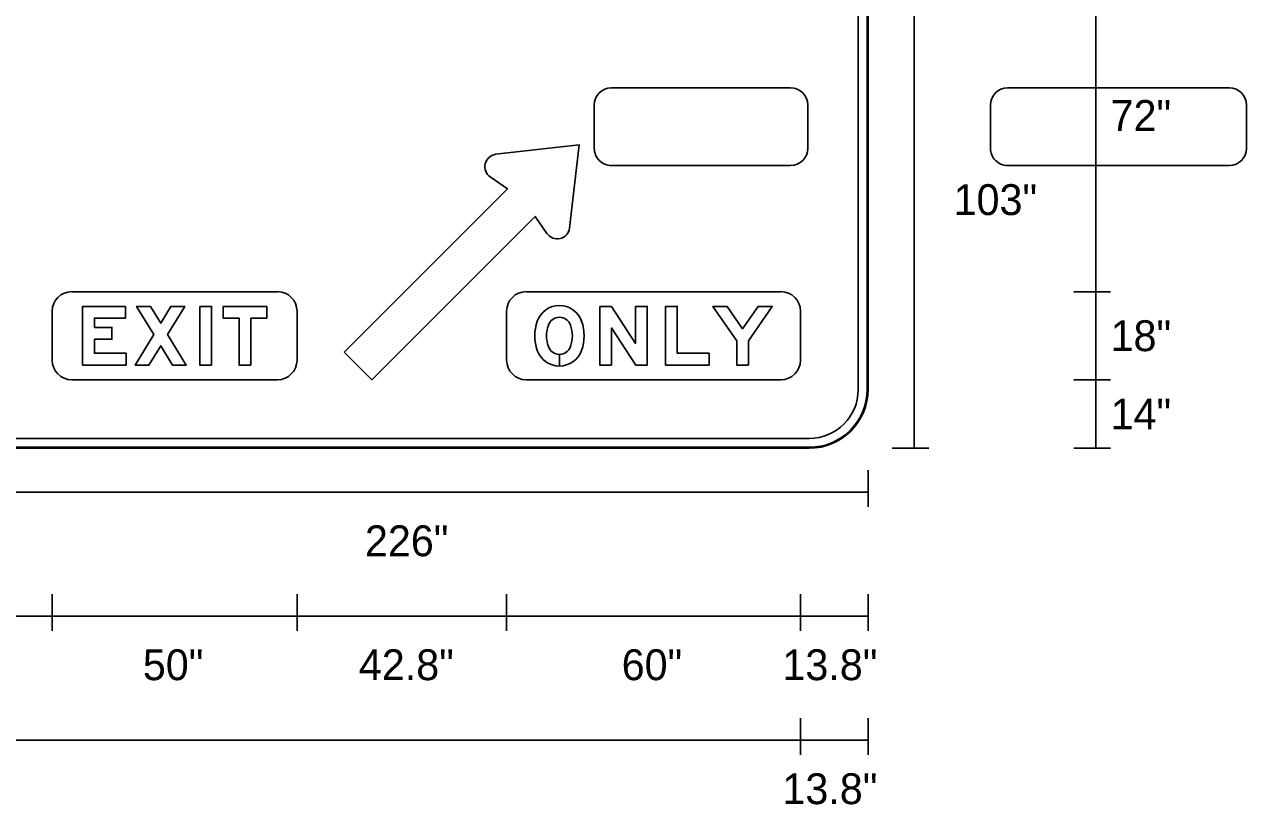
# Model space of a CAD drawing. Extents: x 531799 to 532094, y 1531149 to 1533620.
# Drawn here: x 531850.85 to 531874.42, y 1531200.2 to 1531215.25 of the extents above; entities that cross this region are included whole.
import ezdxf

# ---------------------------------------------------------------- set-up
doc = ezdxf.new("R2010")
doc.units = 0
for name, color, linetype in [('GSDims', 7, 'Continuous'), ('GSOutline', 7, 'Continuous'), ('SignPanel', 7, 'Continuous')]:
    doc.layers.add(name, color=color, linetype=linetype)

msp = doc.modelspace()

# ---------------------------------------------------------------- linework, layer by layer
at = {"layer": 'GSDims'}
for p, q in [((531868.008, 1531207.076), (531868.008, 1531229.171)), ((531871.513, 1531210.097), (531871.513, 1531216.896)), ((531871.088, 1531210.097), (531871.796, 1531210.097)), ((531871.088, 1531210.097), (531871.796, 1531210.097)), ((531871.513, 1531210.097), (531871.513, 1531208.398)), ((531871.088, 1531208.398), (531871.796, 1531208.398)), ((531871.088, 1531208.398), (531871.796, 1531208.398)), ((531871.513, 1531207.076), (531871.513, 1531208.398)), ((531867.583, 1531207.076), (531868.291, 1531207.076)), ((531871.088, 1531207.076), (531871.796, 1531207.076)), ((531867.118, 1531206.651), (531867.118, 1531205.943)), ((531821.609, 1531206.226), (531865.814, 1531206.226)), ((531865.814, 1531206.226), (531867.118, 1531206.226)), ((531851.387, 1531204.259), (531851.387, 1531203.551)), ((531856.108, 1531204.259), (531856.108, 1531203.551)), ((531860.149, 1531204.259), (531860.149, 1531203.551)), ((531865.814, 1531204.259), (531865.814, 1531203.551)), ((531865.814, 1531204.259), (531865.814, 1531203.551)), ((531867.118, 1531204.259), (531867.118, 1531203.551)), ((531821.609, 1531203.835), (531865.814, 1531203.835)), ((531865.814, 1531203.835), (531867.118, 1531203.835)), ((531865.814, 1531201.868), (531865.814, 1531201.16)), ((531865.814, 1531201.868), (531865.814, 1531201.16)), ((531867.118, 1531201.868), (531867.118, 1531201.16)), ((531821.609, 1531201.443), (531865.814, 1531201.443)), ((531865.814, 1531201.443), (531867.118, 1531201.443))]:
    msp.add_line(p, q, dxfattribs=at)
at = {"layer": 'GSOutline'}
for p, q in [((531866.929, 1531208.209), (531866.929, 1531228.038)), ((531867.118, 1531208.209), (531867.118, 1531228.038)), ((531865.626, 1531214.03), (531862.169, 1531214.03)), ((531874.088, 1531214.03), (531869.808, 1531214.03)), ((531861.839, 1531213.696), (531861.839, 1531212.863)), ((531865.955, 1531212.863), (531865.955, 1531213.696)), ((531869.479, 1531213.696), (531869.479, 1531212.863)), ((531874.418, 1531212.863), (531874.418, 1531213.696)), ((531862.169, 1531212.53), (531865.626, 1531212.53)), ((531869.808, 1531212.53), (531874.088, 1531212.53)), ((531817.263, 1531207.265), (531865.985, 1531207.265)), ((531817.263, 1531207.076), (531865.985, 1531207.076))]:
    msp.add_line(p, q, dxfattribs=at)
for radius in [1.133, 0.944]:
    msp.add_arc((531865.985, 1531208.209), radius, 270, 0, dxfattribs=at)
for centre, start_param, end_param in [((531862.169, 1531213.696), 0, 1.570796), ((531865.626, 1531213.696), 4.712389, 6.283185), ((531869.808, 1531213.696), 0, 1.570796), ((531874.088, 1531213.696), 4.712389, 6.283185), ((531862.169, 1531212.863), 1.570796, 3.141593), ((531865.626, 1531212.863), 3.141593, 4.712389), ((531869.808, 1531212.863), 1.570796, 3.141593), ((531874.088, 1531212.863), 3.141593, 4.712389)]:
    msp.add_ellipse(centre, major_axis=(0, 0.333), ratio=0.987826, start_param=start_param, end_param=end_param, dxfattribs=at)
at = {"layer": 'SignPanel'}
for p, q in [((531866.929, 1531228.038), (531866.929, 1531208.209)), ((531866.929, 1531228.038), (531866.929, 1531208.209)), ((531867.099, 1531228.038), (531867.099, 1531208.209)), ((531867.118, 1531208.209), (531867.118, 1531228.038)), ((531867.118, 1531208.209), (531867.118, 1531228.038)), ((531867.118, 1531208.209), (531867.118, 1531228.038)), ((531867.118, 1531208.209), (531867.118, 1531228.038)), ((531851.764, 1531210.097), (531855.73, 1531210.097)), ((531865.437, 1531210.097), (531860.527, 1531210.097)), ((531851.387, 1531208.776), (531851.387, 1531209.72)), ((531856.108, 1531209.72), (531856.108, 1531208.776)), ((531860.149, 1531209.72), (531860.149, 1531208.776)), ((531865.814, 1531208.776), (531865.814, 1531209.72)), ((531861.168, 1531208.661), (531861.168, 1531208.888)), ((531861.168, 1531208.888), (531861.168, 1531208.661)), ((531861.168, 1531208.661), (531861.168, 1531208.888)), ((531861.168, 1531208.888), (531861.168, 1531208.661)), ((531855.73, 1531208.398), (531851.764, 1531208.398)), ((531860.527, 1531208.398), (531865.437, 1531208.398)), ((531865.985, 1531207.095), (531817.263, 1531207.095)), ((531817.263, 1531207.076), (531865.985, 1531207.076)), ((531817.263, 1531207.076), (531865.985, 1531207.076)), ((531865.985, 1531207.265), (531817.265, 1531207.265)), ((531865.985, 1531207.265), (531817.265, 1531207.265)), ((531817.265, 1531207.076), (531865.985, 1531207.076)), ((531817.265, 1531207.076), (531865.985, 1531207.076))]:
    msp.add_line(p, q, dxfattribs=at)
for points in [[(531859.936, 1531212.747), (531861.547, 1531212.931), (531861.364, 1531211.32)], [(531857.014, 1531208.932), (531860.165, 1531212.083), (531859.835, 1531212.311)], [(531860.927, 1531211.219), (531860.699, 1531211.549), (531857.548, 1531208.398), (531857.014, 1531208.932)]]:
    msp.add_lwpolyline(points, dxfattribs=at)
for points in [[(531852.799, 1531209.814), (531852.799, 1531209.588), (531852.199, 1531209.588), (531852.199, 1531209.406), (531852.539, 1531209.406), (531852.539, 1531209.18), (531852.199, 1531209.18), (531852.199, 1531208.908), (531852.811, 1531208.908), (531852.811, 1531208.681), (531851.972, 1531208.681), (531851.972, 1531209.814)], [(531852.799, 1531209.814), (531852.799, 1531209.588), (531852.199, 1531209.588), (531852.199, 1531209.406), (531852.539, 1531209.406), (531852.539, 1531209.18), (531852.199, 1531209.18), (531852.199, 1531208.908), (531852.811, 1531208.908), (531852.811, 1531208.681), (531851.972, 1531208.681), (531851.972, 1531209.814)], [(531852.799, 1531209.814), (531852.799, 1531209.588), (531852.199, 1531209.588), (531852.199, 1531209.406), (531852.539, 1531209.406), (531852.539, 1531209.18), (531852.199, 1531209.18), (531852.199, 1531208.908), (531852.811, 1531208.908), (531852.811, 1531208.681), (531851.972, 1531208.681), (531851.972, 1531209.814)], [(531853.705, 1531208.681), (531853.478, 1531209.053), (531853.251, 1531208.681), (531852.985, 1531208.681), (531853.345, 1531209.271), (531853.014, 1531209.814), (531853.279, 1531209.814), (531853.478, 1531209.488), (531853.677, 1531209.814), (531853.943, 1531209.814), (531853.611, 1531209.271), (531853.971, 1531208.681)], [(531853.705, 1531208.681), (531853.478, 1531209.053), (531853.251, 1531208.681), (531852.985, 1531208.681), (531853.345, 1531209.271), (531853.014, 1531209.814), (531853.279, 1531209.814), (531853.478, 1531209.488), (531853.677, 1531209.814), (531853.943, 1531209.814), (531853.611, 1531209.271), (531853.971, 1531208.681)], [(531853.705, 1531208.681), (531853.478, 1531209.053), (531853.251, 1531208.681), (531852.985, 1531208.681), (531853.345, 1531209.271), (531853.014, 1531209.814), (531853.279, 1531209.814), (531853.478, 1531209.488), (531853.677, 1531209.814), (531853.943, 1531209.814), (531853.611, 1531209.271), (531853.971, 1531208.681)], [(531854.233, 1531209.814), (531854.459, 1531209.814), (531854.459, 1531208.681), (531854.233, 1531208.681)], [(531854.233, 1531209.814), (531854.459, 1531209.814), (531854.459, 1531208.681), (531854.233, 1531208.681)], [(531854.233, 1531209.814), (531854.459, 1531209.814), (531854.459, 1531208.681), (531854.233, 1531208.681)], [(531855.217, 1531208.681), (531854.99, 1531208.681), (531854.99, 1531209.588), (531854.684, 1531209.588), (531854.684, 1531209.814), (531855.522, 1531209.814), (531855.522, 1531209.588), (531855.217, 1531209.588)], [(531855.217, 1531208.681), (531854.99, 1531208.681), (531854.99, 1531209.588), (531854.684, 1531209.588), (531854.684, 1531209.814), (531855.522, 1531209.814), (531855.522, 1531209.588), (531855.217, 1531209.588)], [(531855.217, 1531208.681), (531854.99, 1531208.681), (531854.99, 1531209.588), (531854.684, 1531209.588), (531854.684, 1531209.814), (531855.522, 1531209.814), (531855.522, 1531209.588), (531855.217, 1531209.588)], [(531861.945, 1531209.814), (531862.171, 1531209.814), (531862.636, 1531209.1), (531862.636, 1531209.814), (531862.862, 1531209.814), (531862.862, 1531208.681), (531862.638, 1531208.681), (531862.171, 1531209.399), (531862.171, 1531208.681), (531861.945, 1531208.681)], [(531861.945, 1531209.814), (531862.171, 1531209.814), (531862.636, 1531209.1), (531862.636, 1531209.814), (531862.862, 1531209.814), (531862.862, 1531208.681), (531862.638, 1531208.681), (531862.171, 1531209.399), (531862.171, 1531208.681), (531861.945, 1531208.681)], [(531861.945, 1531209.814), (531862.171, 1531209.814), (531862.636, 1531209.1), (531862.636, 1531209.814), (531862.862, 1531209.814), (531862.862, 1531208.681), (531862.638, 1531208.681), (531862.171, 1531209.399), (531862.171, 1531208.681), (531861.945, 1531208.681)], [(531863.44, 1531208.908), (531864.052, 1531208.908), (531864.052, 1531208.681), (531863.213, 1531208.681), (531863.213, 1531209.814), (531863.44, 1531209.814)], [(531863.44, 1531208.908), (531864.052, 1531208.908), (531864.052, 1531208.681), (531863.213, 1531208.681), (531863.213, 1531209.814), (531863.44, 1531209.814)], [(531863.44, 1531208.908), (531864.052, 1531208.908), (531864.052, 1531208.681), (531863.213, 1531208.681), (531863.213, 1531209.814), (531863.44, 1531209.814)], [(531864.813, 1531208.681), (531864.586, 1531208.681), (531864.586, 1531209.146), (531864.127, 1531209.814), (531864.402, 1531209.814), (531864.699, 1531209.381), (531864.997, 1531209.814), (531865.272, 1531209.814), (531864.813, 1531209.146)], [(531864.813, 1531208.681), (531864.586, 1531208.681), (531864.586, 1531209.146), (531864.127, 1531209.814), (531864.402, 1531209.814), (531864.699, 1531209.381), (531864.997, 1531209.814), (531865.272, 1531209.814), (531864.813, 1531209.146)], [(531864.813, 1531208.681), (531864.586, 1531208.681), (531864.586, 1531209.146), (531864.127, 1531209.814), (531864.402, 1531209.814), (531864.699, 1531209.381), (531864.997, 1531209.814), (531865.272, 1531209.814), (531864.813, 1531209.146)]]:
    msp.add_lwpolyline(points, close=True, dxfattribs=at)
for centre, radius, start, end in [((531859.972, 1531212.509), 0.241, 98.6981, 235.3296), ((531861.126, 1531211.356), 0.241, 214.6704, 351.3019), ((531851.764, 1531209.72), 0.378, 90, 180), ((531855.73, 1531209.72), 0.378, 0, 90), ((531860.527, 1531209.72), 0.378, 90, 180), ((531865.437, 1531209.72), 0.378, 0, 90), ((531861.168, 1531209.377), 0.453, 19.6063, 160.3937), ((531861.168, 1531209.377), 0.453, 19.6063, 160.3937), ((531861.168, 1531209.377), 0.453, 19.6063, 160.3937), ((531861.536, 1531209.246), 0.844, 160.3937, 199.6063), ((531861.536, 1531209.246), 0.844, 160.3938, 199.6063), ((531861.536, 1531209.246), 0.844, 160.3938, 199.6063), ((531861.536, 1531209.246), 0.617, 160.3937, 199.6063), ((531861.536, 1531209.246), 0.617, 160.3937, 199.6063), ((531861.536, 1531209.246), 0.617, 160.3937, 199.6063), ((531861.168, 1531209.377), 0.227, 19.6063, 160.3937), ((531861.168, 1531209.377), 0.227, 19.6063, 160.3937), ((531861.168, 1531209.377), 0.227, 19.6063, 160.3937), ((531860.8, 1531209.246), 0.617, 340.3937, 19.6062), ((531860.8, 1531209.246), 0.617, 340.3937, 19.6062), ((531860.8, 1531209.246), 0.617, 340.3937, 19.6062), ((531860.8, 1531209.246), 0.844, 340.3937, 19.6062), ((531860.8, 1531209.246), 0.844, 340.3938, 19.6063), ((531860.8, 1531209.246), 0.844, 340.3938, 19.6063), ((531861.168, 1531209.115), 0.453, 199.6063, 340.3938), ((531861.168, 1531209.115), 0.453, 199.6063, 270), ((531861.168, 1531209.115), 0.453, 199.6063, 270), ((531861.168, 1531209.115), 0.227, 199.6063, 340.3938), ((531861.168, 1531209.115), 0.227, 199.6063, 270), ((531861.168, 1531209.115), 0.227, 199.6063, 270), ((531861.168, 1531209.115), 0.227, 270.0143, 340.3938), ((531861.168, 1531209.115), 0.227, 270.0143, 340.3938), ((531861.168, 1531209.115), 0.453, 270.0072, 340.3937), ((531861.168, 1531209.115), 0.453, 270.0072, 340.3937), ((531851.764, 1531208.776), 0.378, 180, 270), ((531855.73, 1531208.776), 0.378, 270, 0), ((531860.527, 1531208.776), 0.378, 180, 270), ((531865.437, 1531208.776), 0.378, 270, 0), ((531865.985, 1531208.209), 1.133, 270, 0), ((531865.985, 1531208.209), 1.133, 270, 0), ((531865.985, 1531208.209), 0.944, 270, 0), ((531865.985, 1531208.209), 1.133, 270, 0), ((531865.985, 1531208.209), 0.944, 270, 0), ((531865.985, 1531208.209), 1.133, 270, 0), ((531865.985, 1531208.209), 1.114, 270, 0)]:
    msp.add_arc(centre, radius, start, end, dxfattribs=at)

# ---------------------------------------------------------------- texts
at = {"layer": 'GSDims'}
for s, p in [('72"', (531871.796, 1531213.199)), ('103"', (531868.769, 1531211.575)), ('18"', (531871.796, 1531208.95)), ('14"', (531871.796, 1531207.439)), ('226"', (531857.417, 1531204.993)), ('50"', (531853.134, 1531202.602)), ('42.8"', (531857.3, 1531202.602)), ('60"', (531862.368, 1531202.602)), ('13.8"', (531865.468, 1531202.602)), ('13.8"', (531865.468, 1531200.21))]:
    msp.add_text(s, height=0.595, dxfattribs=at).set_placement(p)

doc.saveas('drawing.dxf')
